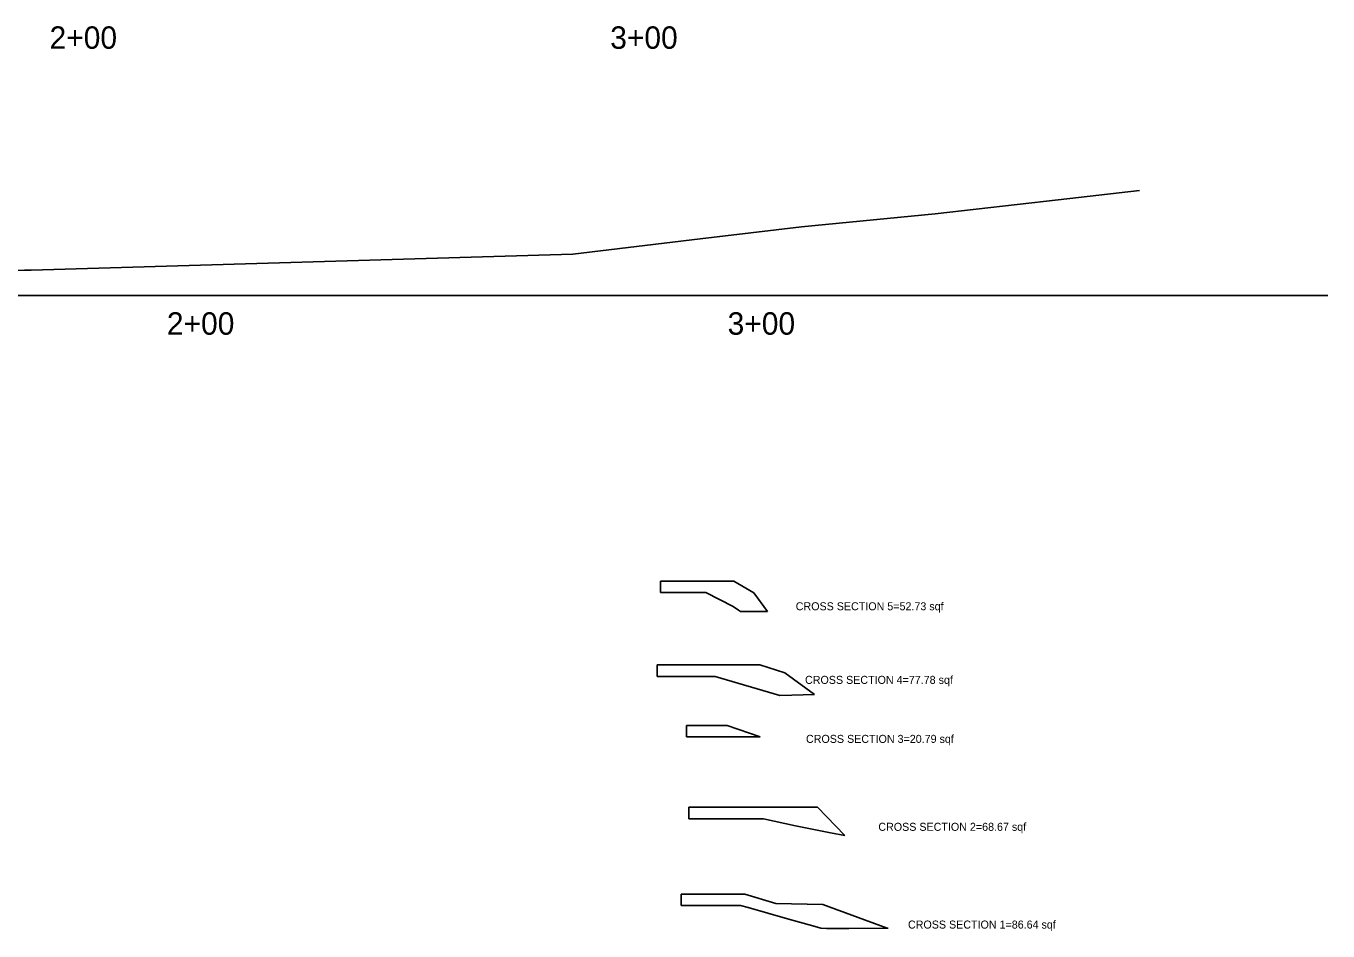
# Model space of a CAD drawing. Extents: x 1578769 to 1579225, y 724002 to 724828.
# Drawn here: x 1578992.8 to 1579225.1, y 724138.8 to 724300.2 of the extents above; entities that cross this region are included whole.
import ezdxf

# ---------------------------------------------------------------- set-up
doc = ezdxf.new("R2010")
doc.units = 0
for name, color, linetype in [('1', 7, 'Continuous'), ('Default', 7, 'Continuous'), ('Old_Level_1', 7, 'Continuous')]:
    doc.layers.add(name, color=color, linetype=linetype)

msp = doc.modelspace()

# ---------------------------------------------------------------- linework, layer by layer
at = {"layer": '1'}
for p, q in [((1579105.99, 724199.12), (1579105.99, 724201.19)), ((1579105.99, 724201.19), (1579119.11, 724201.19)), ((1579119.11, 724201.19), (1579122.65, 724199.07)), ((1579114.08, 724199.12), (1579105.99, 724199.12)), ((1579122.65, 724199.07), (1579125.11, 724195.74)), ((1579120.28, 724195.74), (1579119.92, 724195.98)), ((1579125.11, 724195.74), (1579120.28, 724195.74)), ((1579105.41, 724184.13), (1579105.41, 724186.22)), ((1579105.41, 724186.22), (1579123.73, 724186.22)), ((1579123.73, 724186.22), (1579128.21, 724184.83)), ((1579128.21, 724184.83), (1579133.48, 724180.93)), ((1579115.77, 724184.13), (1579105.41, 724184.13)), ((1579127.32, 724180.76), (1579115.77, 724184.13)), ((1579129.44, 724180.82), (1579127.32, 724180.76)), ((1579117.91, 724175.41), (1579110.64, 724175.41)), ((1579110.64, 724175.41), (1579110.64, 724173.37)), ((1579123.81, 724173.37), (1579117.91, 724175.41)), ((1579110.64, 724173.37), (1579123.81, 724173.37)), ((1579111.07, 724158.74), (1579111.07, 724160.87)), ((1579111.07, 724160.87), (1579115.15, 724160.87)), ((1579124.4, 724158.74), (1579111.07, 724158.74)), ((1579115.15, 724160.87), (1579134.05, 724160.87)), ((1579134.05, 724160.87), (1579138.93, 724155.79)), ((1579109.71, 724143.3), (1579109.71, 724145.3)), ((1579109.71, 724145.3), (1579121.06, 724145.3)), ((1579121.06, 724145.3), (1579126.62, 724143.66)), ((1579120.27, 724143.3), (1579109.71, 724143.3)), ((1579126.62, 724143.66), (1579135, 724143.49)), ((1579135, 724143.49), (1579146.45, 724139.27)), ((1579146.45, 724139.27), (1579146.45, 724139.27)), ((1579146.45, 724139.27), (1579146.62, 724139.27))]:
    msp.add_line(p, q, dxfattribs=at)
for points in [[(1579119.92, 724195.98), (1579118.96, 724196.62), (1579114.08, 724199.12)], [(1579133.48, 724180.93), (1579129.44, 724180.82)], [(1579138.93, 724155.79), (1579136.37, 724156.29), (1579130.08, 724157.53), (1579124.4, 724158.74)], [(1579146.62, 724139.27), (1579139.62, 724139.22), (1579135.67, 724139.19), (1579134.62, 724139.27), (1579133.64, 724139.57), (1579128.69, 724140.93), (1579121.64, 724142.91), (1579120.27, 724143.3)]]:
    msp.add_lwpolyline(points, dxfattribs=at)
at = {"layer": 'Default'}
msp.add_line((1578825.14, 724252.14), (1579225.14, 724252.14), dxfattribs=at)
msp.add_lwpolyline([(1578826.03, 724272.5), (1578843.36, 724272.54), (1578848.22, 724272.56), (1578852.66, 724272.6), (1578873.81, 724272.68), (1578875.71, 724271.56), (1578889.52, 724263.07), (1578894.2, 724261.45), (1578913.46, 724256.02), (1578914.49, 724256.05), (1578915.04, 724256.06), (1578992.5, 724256.63), (1578992.52, 724256.63), (1578992.57, 724256.63), (1578992.74, 724256.64), (1578993.71, 724256.67), (1579090.36, 724259.53), (1579113.09, 724262.23), (1579131.18, 724264.4), (1579155.02, 724266.72), (1579177.01, 724269.23), (1579191.53, 724270.88)], dxfattribs=at)

# ---------------------------------------------------------------- texts
for s, p in [('2+00', (1578996.98, 724296.15)), ('3+00', (1579097.04, 724296.15)), ('2+00', (1579017.92, 724245.14)), ('3+00', (1579117.99, 724245.14))]:
    msp.add_text(s, height=4, dxfattribs=at).set_placement(p)
at = {"layer": 'Old_Level_1'}
for s, p in [('CROSS SECTION 5=52.73 sqf', (1579130.15, 724195.97)), ('CROSS SECTION 4=77.78 sqf', (1579131.81, 724182.84)), ('CROSS SECTION 3=20.79 sqf', (1579131.98, 724172.31)), ('CROSS SECTION 2=68.67 sqf', (1579144.89, 724156.62)), ('CROSS SECTION 1=86.64 sqf', (1579150.18, 724139.18))]:
    msp.add_text(s, height=1.4286, dxfattribs=at).set_placement(p)

doc.saveas('drawing.dxf')
